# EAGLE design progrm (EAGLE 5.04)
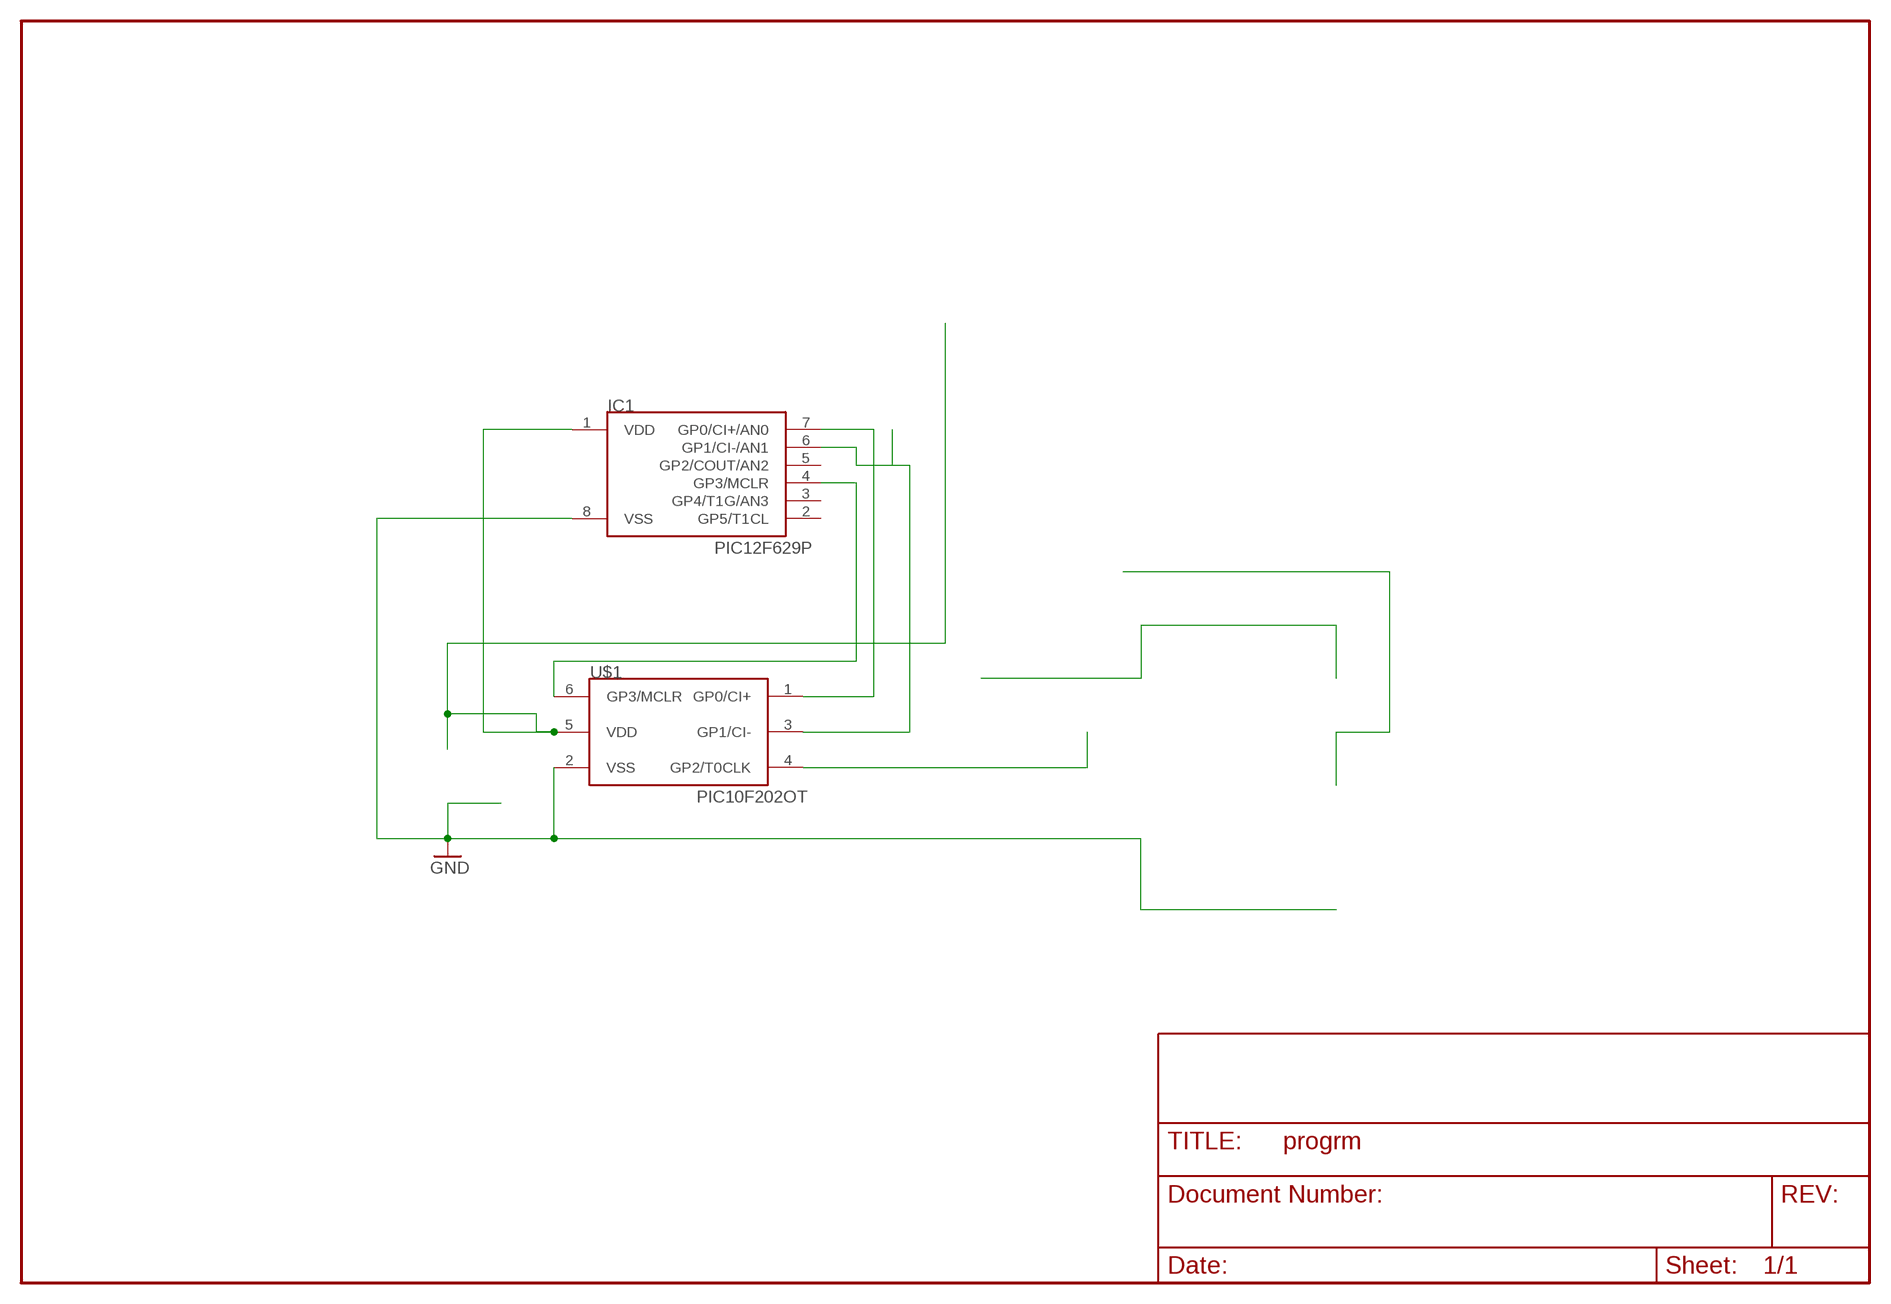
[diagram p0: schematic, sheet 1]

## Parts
IC1  PIC12F629P  [DIL8]
U$1  PIC10F202OT  [SOT23-6]

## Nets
GND: IC1.8(VSS) U$1.2(VSS)
N$8: IC1.1(VDD) U$1.5(VDD)
N$9: IC1.7(GP0/CI+/AN0) U$1.1(GP0/CI+)
N$10: IC1.6(GP1/CI-/AN1) U$1.3(GP1/CI-)
N$12: IC1.4(GP3/MCLR) U$1.6(GP3/MCLR)
N$14: U$1.4(GP2/T0CLK)
Unconnected: IC1.2(GP5/T1CL) IC1.3(GP4/T1G/AN3) IC1.5(GP2/COUT/AN2)

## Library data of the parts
IC1 = microchip-5:PIC12F6*: uPC nW 1k Program Flash memory 2x Timer Comparator 10b A/D converter/ 4xIN
U$1 = microchip-3:PIC10F2*: uPC nW 0,25/0,5k Program Flash memory Comparator

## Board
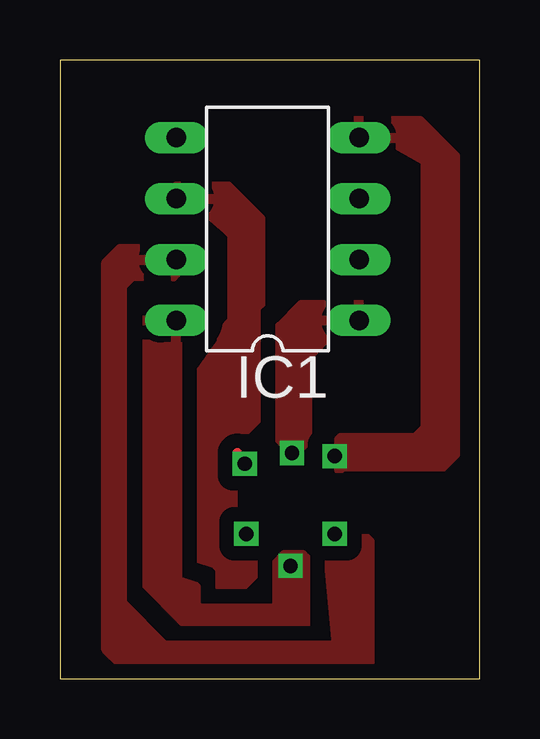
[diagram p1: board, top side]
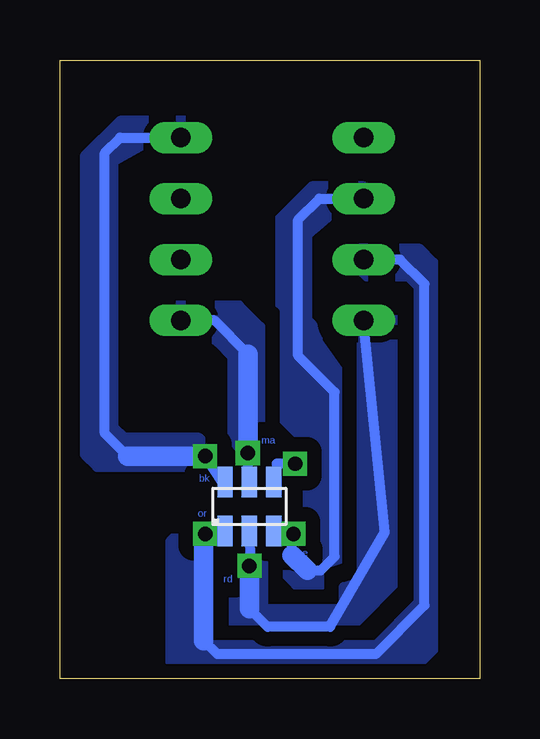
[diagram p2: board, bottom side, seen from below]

Size 17.51 x 25.77 mm. Coordinates in mm from the lower left corner, seen from the top.
Outline: 0,0 17.51,0 17.51,25.77 0,25.77 0,0
Copper layers (1*16): Top 0.035mm / dielectric 1.5mm / Bottom 0.035mm
Design rules "default": minimum track width 12mil, minimum drill 24mil, track to track 8mil, track to pad 8mil, pad to pad 8mil, via to via 8mil, smd to smd 8mil, copper to edge 16mil, drill to drill 8mil, minimum pad ring 10mil, minimum via ring 8mil, stop-mask expansion 4mil, vias tented up to drill 0mil, thermal gap 10mil

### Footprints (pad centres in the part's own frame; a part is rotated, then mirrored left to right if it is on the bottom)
DIL8 = drill 0.813 long: 1 -3.81,-3.81; 2 -1.27,-3.81; 3 1.27,-3.81; 4 3.81,-3.81; 5 3.81,3.81; 6 1.27,3.81; 7 -1.27,3.81; 8 -3.81,3.81
SOT23-6 = smd 0.635 x 1.27: 1 -1.016,-1.016; 2 0,-1.016; 3 1.016,-1.016; 4 1.016,1.016; 5 0,1.016; 6 -1.016,1.016

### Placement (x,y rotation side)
IC1  8.66,18.73 90 top
U$1  9.61,7.17 0 bottom

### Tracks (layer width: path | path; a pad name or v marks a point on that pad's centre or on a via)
GND  (via drill 0.6)
  Top 0.406: v9.61,4.69 9.61,4.63
  Bottom 0.406: 9.55,4.76 U$1.2 | v9.61,4.69 9.55,4.76 | v9.61,4.69 9.68,4.83 9.68,4.82 | 9.55,4.76 9.68,4.76 9.61,4.82 v9.61,4.69 | 9.68,4.82 | v9.61,4.69 9.68,4.82 | IC1.8 3.96,6.09 6.25,2.15 8.85,2.15 9.61,2.92
  Bottom 0.813: 9.61,2.92 v9.61,4.69
  pour Bottom (isolate 0.61, rank 2): 3.65,15.11 3.65,2.34 4.66,1.9 10.19,1.9 10.25,1.84 10.25,5.01 10.12,5.14 9.36,5.14 9.04,4.82 9.04,2.98 8.98,2.92 5.8,2.92 5.68,3.04 5.68,3.81 4.92,4.06 4.92,14.54
  pour Top (isolate 0.61, rank 2): 3.65,15.11 3.65,2.34 4.66,1.9 10.19,1.9 10.25,1.84 10.25,5.01 10.12,5.14 9.36,5.14 9.04,4.82 9.04,2.98 8.98,2.92 5.8,2.92 5.68,3.04 5.68,3.81 4.92,4.06 4.92,14.54
N$2  (via drill 0.6)
  other vias: 7.77,6.03
N$3  (via drill 0.6)
  other vias: 11.46,6.03
N$8  (via drill 0.6)
  Bottom 0.254: U$1.5 9.68,8.63
  Bottom 0.406: 9.68,8.63 v9.68,9.39 | IC1.1 11.07,14.92 9.68,13.52
  Bottom 0.813: v9.68,9.39 9.68,13.52
  pour Bottom (isolate 0.61, rank 2): 13.3,15.55 10.06,15.55 9.17,14.66 9.17,9.96 9.55,9.58 9.99,9.58 10.31,9.9 10.31,13.39 10.95,14.03
  pour Top (isolate 0.61, rank 2): 13.3,15.55 10.06,15.55 9.17,14.66 9.17,9.96 9.55,9.58 9.99,9.58 10.31,9.9 10.31,13.39 10.95,14.03
N$9
  Bottom 0.406: IC1.7 3.33,17.46 2.31,16.44 2.31,3.04 4.34,1.01 10.95,1.01 11.52,1.58 | 11.52,5.96 11.58,6.03 10.76,6.03 U$1.1
  Bottom 0.813: 11.52,1.58 11.52,5.96
  pour Bottom (isolate 0.61): 11.07,6.54 12.09,6.54 12.92,5.71 12.92,0.69 12.85,0.63 2.5,0.63 1.93,1.2 1.93,17.33 2.5,17.9 5.04,17.9 5.49,17.46 5.42,17.46 4.72,16.76 3.01,16.76 2.57,16.31 2.57,3.17 4.34,1.39 11.39,1.39 11.58,1.2
  pour Top (isolate 0.61): 11.07,6.54 12.09,6.54 12.92,5.71 12.92,0.69 12.85,0.63 2.5,0.63 1.93,1.2 1.93,17.33 2.5,17.9 5.04,17.9 5.49,17.46 5.42,17.46 4.72,16.76 3.01,16.76 2.57,16.31 2.57,3.17 4.34,1.39 11.39,1.39 11.58,1.2
N$10
  Bottom 0.406: IC1.6 6.69,20 7.58,19.11 7.58,13.46 6.06,11.93 6.06,5.08 6.63,4.5 7.2,4.5 | 7.84,5.14 7.84,6.16 U$1.3
  Bottom 0.813: 7.2,4.5 7.84,5.14
  pour Bottom (isolate 0.61, rank 3): 4.85,20.51 7.01,20.51 8.34,19.17 8.34,10.92 7.2,9.77 7.2,7.3 8.22,6.28 8.22,4.44 7.26,3.49 6.69,3.49 5.68,4.57 5.68,12.5 6.76,14.03 6.76,14.47 7.2,14.92 7.2,18.47 6.95,18.73
  pour Top (isolate 0.61, rank 3): 4.85,20.51 7.01,20.51 8.34,19.17 8.34,10.92 7.2,9.77 7.2,7.3 8.22,6.28 8.22,4.44 7.26,3.49 6.69,3.49 5.68,4.57 5.68,12.5 6.76,14.03 6.76,14.47 7.2,14.92 7.2,18.47 6.95,18.73
N$12  (via drill 0.6)
  Top 0.406: v11.46,9.27 11.46,9.52
  Bottom 0.406: U$1.6 10.76,8.19 v11.46,9.27 11.52,9.27 11.65,9.39 | IC1.4 15.01,22.54 15.65,21.9 15.65,10.22 14.69,9.27
  Bottom 0.813: v11.46,9.27 14.69,9.27
  pour Bottom (isolate 0.61): 12.28,23.24 15.01,23.24 16.47,21.78 16.47,9.33 15.96,8.82 11.77,8.82 11.65,8.69 11.65,9.96 11.71,10.03 14.82,10.03 15.27,10.47 15.27,21.52 15.2,21.59
  pour Top (isolate 0.61): 12.28,23.24 15.01,23.24 16.47,21.78 16.47,9.33 15.96,8.82 11.77,8.82 11.65,8.69 11.65,9.96 11.71,10.03 14.82,10.03 15.27,10.47 15.27,21.52 15.2,21.59
N$14  (via drill 0.6)
  Top 0.406: 7.39,9.39 v7.71,8.95
  Bottom 0.406: U$1.4 8.47,8.95 v7.71,8.95

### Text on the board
Bottom: ma | bk | or | ye | rd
